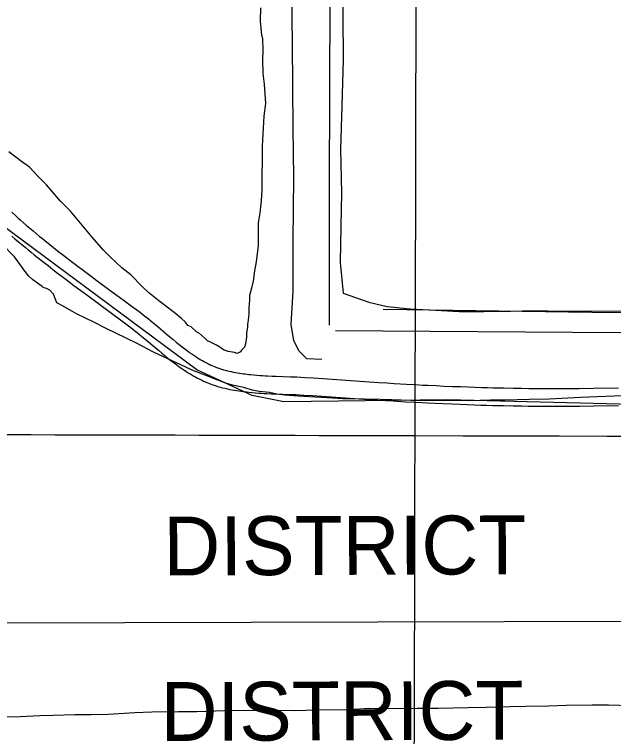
# Model space of a CAD drawing. Extents: x 3180038 to 3217926, y 922069 to 947485.
# Drawn here: x 3186224 to 3187243, y 939132 to 940353 of the extents above; entities that cross this region are included whole.
import ezdxf

# ---------------------------------------------------------------- set-up
doc = ezdxf.new("R2010")
doc.units = 0
for name, color, linetype in [('V-GRID-MAJR', 7, 'Continuous'), ('V-ROAD-CNTR', 7, 'Continuous'), ('V-SITE-VEGE', 7, 'Continuous'), ('V-TOPO-BNDY', 7, 'Continuous'), ('V-TOPO-GNAM-IDEN', 7, 'Continuous'), ('V-TOPO-SHOR', 7, 'Continuous')]:
    doc.layers.add(name, color=color, linetype=linetype)

msp = doc.modelspace()

# ---------------------------------------------------------------- linework, layer by layer
at = {"layer": 'V-GRID-MAJR'}
for points in [[(3186873.701, 927512.849), (3186889.572, 933574.8250000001), (3186905.4450000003, 939637.892), (3186921.319, 945701.009), (3186921.322, 945702.052)], [(3184296.343, 939644.818), (3186905.4450000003, 939637.892), (3192123.65, 939624.61), (3197341.857, 939612.087), (3202560.066, 939600.323), (3207778.276, 939589.318), (3212996.488, 939579.072), (3215605.594, 939574.233)]]:
    msp.add_spline(points, degree=3, dxfattribs=at)
at = {"layer": 'V-ROAD-CNTR'}
for points in [[(3186746.885000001, 939767.4489999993), (3186721.199000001, 939768.0739999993), (3186708.247000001, 939781.1749999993), (3186699.546000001, 939798.6749999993), (3186694.671000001, 939826.5769999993), (3186698.024000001, 939883.5709999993), (3186698.067000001, 939968.6919999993), (3186699.183000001, 940076.4899999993), (3186698.128000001, 940160.1839999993), (3186697.422000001, 940230.9029999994), (3186696.983000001, 940304.3829999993), (3186696.046000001, 940387.7139999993), (3186696.594000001, 940475.4709999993), (3186697.387000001, 940574.9899999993), (3186699.457000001, 940693.8269999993), (3186700.256000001, 940805.5919999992), (3186701.929000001, 940943.8819999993), (3186703.848000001, 941059.5979999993), (3186705.089000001, 941213.9799999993), (3186705.210000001, 941341.5989999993)], [(3186219.9015233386, 940017.2039377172), (3186226.0895109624, 940011.5429490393), (3186230.746501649, 940007.3529574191), (3186234.2434946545, 940004.2479636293), (3186239.549484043, 939999.6089729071), (3186244.9024733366, 939995.0179820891), (3186250.612461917, 939990.1959917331), (3186256.177450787, 939985.5450010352), (3186261.5914399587, 939981.0650099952), (3186266.8574294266, 939976.7480186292), (3186271.975419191, 939972.5860269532), (3186276.9494092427, 939968.5740349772), (3186281.774399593, 939964.7110427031), (3186291.1893807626, 939957.2480576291), (3186300.050363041, 939950.307071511), (3186308.3943463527, 939943.8400844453), (3186316.2473306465, 939937.8050965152), (3186323.6343158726, 939932.1711077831), (3186330.5733019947, 939926.9131182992), (3186343.655275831, 939917.0771379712), (3186355.139252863, 939908.5111551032), (3186365.216232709, 939901.0331700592), (3186382.9261972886, 939887.9531962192)], [(3186219.911523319, 939976.9290182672), (3186225.4585122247, 939972.1720277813), (3186231.3145005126, 939967.2260376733), (3186236.997489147, 939962.4770471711), (3186242.5194781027, 939957.909056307), (3186247.883467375, 939953.5100651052), (3186253.095456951, 939949.2720735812), (3186258.157446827, 939945.1900817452), (3186263.080436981, 939941.2470896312), (3186272.6214178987, 939933.684104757), (3186281.6103999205, 939926.643118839), (3186290.0643830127, 939920.0901319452), (3186298.011367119, 939913.9831441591), (3186305.478352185, 939908.2891555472), (3186312.499338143, 939902.9691661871), (3186325.6713117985, 939893.0651859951), (3186337.231288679, 939884.441203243), (3186347.366268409, 939876.9212182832), (3186365.104232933, 939863.8212444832)], [(3186382.913197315, 939887.9631961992), (3186409.5611440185, 939868.3282354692), (3186422.908117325, 939858.4692551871), (3186436.270090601, 939848.5532750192), (3186438.6850857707, 939846.7422786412), (3186443.3670764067, 939843.1562858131), (3186447.875067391, 939839.6192928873), (3186452.2000587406, 939836.1562998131), (3186456.357050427, 939832.772306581), (3186460.364042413, 939829.4653131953), (3186468.0190271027, 939823.0583260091), (3186482.216998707, 939811.0353500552), (3186488.3859863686, 939805.8353604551), (3186494.154974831, 939801.0273700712), (3186499.560964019, 939796.5933789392), (3186504.6339538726, 939792.5163870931), (3186509.3979443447, 939788.7733945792), (3186513.8759353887, 939785.3454014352), (3186518.086926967, 939782.2094077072), (3186522.0489190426, 939779.3444134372), (3186525.776911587, 939776.7294186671), (3186529.2879045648, 939774.3444234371), (3186532.592897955, 939772.1684277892), (3186535.7078917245, 939770.1844317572), (3186538.639885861, 939768.3764353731), (3186541.397880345, 939766.7294386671), (3186543.9988751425, 939765.226441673), (3186546.445870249, 939763.8564444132), (3186548.7488656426, 939762.6094469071), (3186550.9208612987, 939761.4684491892), (3186552.964857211, 939760.4274512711), (3186554.886853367, 939759.477453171), (3186556.695849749, 939758.6094549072), (3186558.3958463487, 939757.8164564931), (3186559.9638432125, 939757.1064579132), (3186563.029837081, 939755.772460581), (3186565.6878317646, 939754.6744627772), (3186568.028827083, 939753.7554646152), (3186570.091822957, 939752.9804661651), (3186571.900819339, 939752.3284674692), (3186573.4578162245, 939751.7894685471), (3186576.3128105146, 939750.8504704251), (3186578.426806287, 939750.1964717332), (3186579.9898031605, 939749.7364726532), (3186582.420798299, 939749.0594740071), (3186584.8527934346, 939748.4274752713), (3186588.8147855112, 939747.4744771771), (3186592.662777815, 939746.6164788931), (3186596.404770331, 939745.8424804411), (3186600.039763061, 939745.144481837), (3186603.5707559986, 939744.516483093), (3186607.001749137, 939743.9504842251), (3186610.335742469, 939743.4394852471), (3186613.572735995, 939742.9784861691), (3186616.7167297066, 939742.563486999), (3186619.771723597, 939742.1874877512), (3186622.737717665, 939741.8474884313), (3186625.5937119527, 939741.5434890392), (3186631.223700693, 939741.0034901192), (3186636.495690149, 939740.5624910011), (3186641.4596802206, 939740.1994917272), (3186646.130670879, 939739.8964923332), (3186650.522662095, 939739.6434928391), (3186654.6416538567, 939739.4294932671), (3186662.445638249, 939739.0754939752), (3186669.284624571, 939738.8064945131), (3186693.4935761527, 939737.9454962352), (3186699.607563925, 939737.7014967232), (3186704.221554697, 939737.4974971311), (3186711.136540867, 939737.1514978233), (3186718.048527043, 939736.7444986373), (3186732.9034973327, 939735.7815005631), (3186843.800275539, 939728.3105155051), (3186857.629247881, 939727.4185172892), (3186869.7302236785, 939726.6595188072), (3186890.921181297, 939725.3875213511), (3186906.8061495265, 939724.4895231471), (3186918.718125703, 939723.8545244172), (3186927.643107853, 939723.4005253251), (3186941.047081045, 939722.759526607), (3186954.4530542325, 939722.1705277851), (3186968.835025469, 939721.5835289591), (3186982.323998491, 939721.0645299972), (3186994.9669732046, 939720.6055309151), (3187006.818949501, 939720.201531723), (3187017.927927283, 939719.8475324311), (3187028.3579064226, 939719.5365330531)], [(3186365.117232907, 939863.811244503), (3186391.751179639, 939844.1862837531), (3186405.058153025, 939834.3573034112), (3186418.332126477, 939824.5073231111), (3186420.5651220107, 939822.8323264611), (3186424.987113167, 939819.4463332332), (3186429.239104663, 939816.1093399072), (3186433.3540964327, 939812.8143464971), (3186437.3390884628, 939809.5703529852), (3186441.188080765, 939806.3933593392), (3186448.6990657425, 939800.1083719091), (3186462.8550374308, 939788.1193958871), (3186469.114024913, 939782.8434064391), (3186475.0390130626, 939777.9054163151), (3186480.651001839, 939773.3034255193), (3186485.969991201, 939769.0284340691), (3186491.0119811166, 939765.0674419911), (3186495.797971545, 939761.4034493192), (3186500.3369624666, 939758.0234560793), (3186504.6449538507, 939754.9084623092), (3186508.732945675, 939752.0414680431), (3186512.6099379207, 939749.4064733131), (3186516.2869305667, 939746.9864781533), (3186519.771923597, 939744.766482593), (3186523.0739169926, 939742.7284866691), (3186526.2059107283, 939740.8594904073), (3186529.1689048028, 939739.1484938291), (3186531.973899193, 939737.5784969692), (3186534.628893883, 939736.1394998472), (3186537.136888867, 939734.8225024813), (3186539.508884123, 939733.6135048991), (3186541.750879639, 939732.5055071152), (3186543.867875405, 939731.4895091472), (3186545.8698714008, 939730.5565110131), (3186547.7918675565, 939729.6865127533), (3186551.315860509, 939728.1525158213), (3186554.477854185, 939726.8465184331), (3186557.2708485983, 939725.7495206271), (3186559.733843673, 939724.8245224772), (3186561.9108393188, 939724.0405240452), (3186563.861835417, 939723.3655253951), (3186567.192828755, 939722.2685275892), (3186569.756823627, 939721.4765291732), (3186571.7238196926, 939720.8965303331), (3186574.6268138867, 939720.0875319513), (3186577.5748079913, 939719.3235334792), (3186582.038799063, 939718.248535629), (3186586.3607904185, 939717.2845375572), (3186590.5407820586, 939716.4205392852), (3186594.5857739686, 939715.644540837), (3186598.500766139, 939714.9485422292), (3186602.285758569, 939714.3225434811), (3186605.9477512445, 939713.7615446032), (3186609.492744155, 939713.256545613), (3186612.920737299, 939712.803546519), (3186616.235730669, 939712.3955473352), (3186619.4437242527, 939712.0295480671), (3186622.5717179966, 939711.6955487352), (3186628.541706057, 939711.1235498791), (3186634.149694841, 939710.654550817), (3186639.3936843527, 939710.2695515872), (3186644.296674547, 939709.9525522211), (3186648.882665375, 939709.687552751), (3186653.1856567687, 939709.4655531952), (3186661.1756407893, 939709.1015539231), (3186668.162626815, 939708.8265544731), (3186692.361578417, 939707.9675561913), (3186698.347566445, 939707.7275566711), (3186702.809557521, 939707.5315570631), (3186709.504544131, 939707.1955577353), (3186716.1965307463, 939706.802558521), (3186730.925501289, 939705.8475604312), (3186841.8262794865, 939698.3745753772), (3186855.725251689, 939697.4785771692), (3186867.892227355, 939696.7155786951), (3186889.177184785, 939695.4375812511), (3186905.1601528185, 939694.535583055), (3186917.1561288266, 939693.8945843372), (3186926.165110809, 939693.4365852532), (3186939.671083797, 939692.7915865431), (3186953.1830567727, 939692.196587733), (3186967.647027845, 939691.6075889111), (3186981.202000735, 939691.0845899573), (3186993.9129753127, 939690.6235908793), (3187005.8309514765, 939690.2175916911), (3187017.0039291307, 939689.8615924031), (3187027.465908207, 939689.5505930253)], [(3187028.324906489, 939719.537533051), (3187038.0958869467, 939719.2685335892), (3187056.4058503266, 939718.8175344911), (3187072.413818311, 939718.4865351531), (3187086.4207902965, 939718.248535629), (3187098.674765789, 939718.0795359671), (3187109.3947443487, 939717.9635361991), (3187118.765725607, 939717.888536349), (3187135.1886927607, 939717.8145364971), (3187147.494668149, 939717.8105365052), (3187156.715649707, 939717.8375364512), (3187170.563622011, 939717.9245362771), (3187184.412594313, 939718.0745359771), (3187208.5075461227, 939718.4085353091), (3187250.717461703, 939719.0715339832)], [(3187027.4989081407, 939689.5495930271), (3187037.3138885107, 939689.2785935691), (3187055.7258516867, 939688.825594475), (3187071.849819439, 939688.4925951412), (3187085.9587912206, 939688.2525956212), (3187098.306766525, 939688.0815959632), (3187109.1127449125, 939687.9655961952), (3187118.5777259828, 939687.8885963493), (3187135.1166929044, 939687.8145964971), (3187147.5326680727, 939687.8105965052), (3187156.853649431, 939687.837596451), (3187170.8196214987, 939687.9265962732), (3187184.7825935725, 939688.076595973), (3187208.951545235, 939688.4125953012), (3187251.2034607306, 939689.0755939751)]]:
    msp.add_lwpolyline(points, dxfattribs=at)
at = {"layer": 'V-SITE-VEGE'}
for p, q in [((3186642.4820000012, 940364.6739999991), (3186642.304000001, 940342.0559999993)), ((3186642.304000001, 940342.0559999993), (3186644.5360000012, 940317.8019999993)), ((3186644.5360000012, 940317.8019999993), (3186646.1070000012, 940312.1349999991)), ((3186646.1070000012, 940312.1349999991), (3186646.756000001, 940291.9309999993)), ((3186646.756000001, 940291.9309999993), (3186645.827000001, 940276.589999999)), ((3186645.827000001, 940276.589999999), (3186646.449000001, 940253.1569999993)), ((3186646.449000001, 940253.1569999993), (3186648.726000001, 940234.5569999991)), ((3186648.726000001, 940234.5569999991), (3186650.895000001, 940202.224999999)), ((3186650.895000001, 940202.224999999), (3186648.300000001, 940180.4299999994)), ((3186648.300000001, 940180.4299999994), (3186646.4430000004, 940149.7449999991)), ((3186646.443000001, 940149.7449999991), (3186645.474000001, 940129.5579999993)), ((3186645.474000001, 940129.5579999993), (3186644.889000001, 940055.2359999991)), ((3186236.480000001, 940103.699999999), (3186214.796000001, 940120.0289999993)), ((3186250.137000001, 940093.8959999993), (3186236.480000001, 940103.699999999)), ((3186264.556000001, 940078.435999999), (3186250.137000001, 940093.8959999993)), ((3186278.983000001, 940063.7779999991), (3186264.556000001, 940078.435999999)), ((3186303.002000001, 940036.1199999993), (3186278.983000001, 940063.7779999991)), ((3186644.889000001, 940055.2359999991), (3186643.934000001, 940036.662999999)), ((3186319.832000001, 940019.0209999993), (3186303.002000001, 940036.1199999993)), ((3186643.934000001, 940036.662999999), (3186641.352000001, 940016.4859999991)), ((3186356.649000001, 939975.1079999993), (3186319.832000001, 940019.0209999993)), ((3186641.352000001, 940016.4859999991), (3186638.794000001, 939999.5409999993)), ((3186638.794000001, 939999.5409999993), (3186638.4890000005, 939960.7639999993)), ((3186375.865000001, 939953.1409999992), (3186356.649000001, 939975.1079999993)), ((3186224.4590000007, 939941.4469999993), (3186202.8260000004, 939964.2389999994)), ((3186387.887000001, 939940.9289999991), (3186375.865000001, 939953.1409999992)), ((3186638.489000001, 939960.7639999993), (3186635.040000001, 939933.3229999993)), ((3186232.454000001, 939930.8829999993), (3186224.459000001, 939941.4469999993)), ((3186407.134000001, 939923.0029999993), (3186387.887000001, 939940.9289999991)), ((3186236.4480000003, 939925.1939999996), (3186232.454000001, 939930.8829999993)), ((3186635.040000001, 939933.3229999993), (3186632.494000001, 939917.9929999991)), ((3186238.0450000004, 939922.7589999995), (3186236.4480000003, 939925.1939999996)), ((3186240.443000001, 939919.5089999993), (3186238.0450000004, 939922.7589999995)), ((3186249.246000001, 939908.9369999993), (3186240.443000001, 939919.5089999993)), ((3186422.388000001, 939910.763999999), (3186407.134000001, 939923.0029999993)), ((3186632.494000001, 939917.9929999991), (3186629.932000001, 939900.238999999)), ((3186255.658000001, 939902.4219999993), (3186249.246000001, 939908.9369999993)), ((3186267.710000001, 939894.2489999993), (3186255.658000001, 939902.4219999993)), ((3186441.622000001, 939891.2239999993), (3186422.388000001, 939910.763999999)), ((3186271.724000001, 939890.9859999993), (3186267.710000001, 939894.2489999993)), ((3186273.328000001, 939889.3559999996), (3186271.724000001, 939890.9859999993)), ((3186278.9700000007, 939887.6969999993), (3186273.328000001, 939889.3559999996)), ((3186452.850000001, 939880.6319999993), (3186441.622000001, 939891.2239999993)), ((3186629.932000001, 939900.238999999), (3186627.413000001, 939888.1419999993)), ((3186284.6060000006, 939885.2289999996), (3186278.9700000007, 939887.6969999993)), ((3186291.0130000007, 939877.9079999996), (3186284.6060000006, 939885.2289999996)), ((3186296.552000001, 939863.3219999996), (3186291.0130000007, 939877.9079999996)), ((3186469.707000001, 939866.7649999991), (3186452.8500000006, 939880.631999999)), ((3186627.413000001, 939888.1419999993), (3186624.085000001, 939876.047999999)), ((3186476.938000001, 939861.8599999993), (3186469.707000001, 939866.7649999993)), ((3186624.028000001, 939868.7799999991), (3186623.112000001, 939855.0519999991)), ((3186624.085000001, 939876.047999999), (3186624.028000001, 939868.7799999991)), ((3186298.969000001, 939862.4949999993), (3186296.552000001, 939863.3219999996)), ((3186306.2070000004, 939858.3989999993), (3186298.969000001, 939862.4949999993)), ((3186323.097000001, 939848.5699999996), (3186306.207000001, 939858.3989999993)), ((3186491.391000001, 939850.4359999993), (3186476.938000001, 939861.8599999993)), ((3186623.112000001, 939855.0519999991), (3186623.022000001, 939843.7409999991)), ((3186331.139000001, 939844.4659999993), (3186323.097000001, 939848.5699999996)), ((3186359.307000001, 939830.5109999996), (3186331.139000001, 939844.4659999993)), ((3186496.212000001, 939847.1649999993), (3186491.391000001, 939850.4359999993)), ((3186508.246000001, 939836.5689999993), (3186496.212000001, 939847.1649999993)), ((3186623.022000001, 939843.7409999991), (3186621.300000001, 939830.020999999)), ((3186381.837000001, 939819.0239999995), (3186359.307000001, 939830.5109999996)), ((3186515.471000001, 939830.856999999), (3186508.246000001, 939836.5689999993)), ((3186519.467000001, 939825.1699999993), (3186515.471000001, 939830.856999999)), ((3186621.300000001, 939830.020999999), (3186620.472000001, 939827.6049999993)), ((3186413.2290000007, 939804.2329999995), (3186381.837000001, 939819.0239999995)), ((3186525.101000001, 939822.7019999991), (3186519.4670000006, 939825.1699999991)), ((3186534.727000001, 939813.7399999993), (3186525.101000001, 939822.7019999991)), ((3186620.427000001, 939821.9499999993), (3186618.736000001, 939812.2669999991)), ((3186620.472000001, 939827.6049999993), (3186620.427000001, 939821.9499999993)), ((3186433.349000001, 939794.3799999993), (3186413.2290000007, 939804.2329999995)), ((3186538.747000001, 939811.283999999), (3186534.727000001, 939813.7399999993)), ((3186548.377000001, 939803.1289999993), (3186538.747000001, 939811.283999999)), ((3186618.676000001, 939804.998999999), (3186616.972000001, 939793.6999999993)), ((3186618.736000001, 939812.2669999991), (3186618.676000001, 939804.998999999)), ((3186460.700000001, 939779.6219999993), (3186433.349000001, 939794.3799999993)), ((3186552.384000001, 939799.0579999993), (3186548.377000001, 939803.1289999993)), ((3186556.4110000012, 939797.408999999), (3186552.384000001, 939799.0579999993)), ((3186562.043000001, 939794.133999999), (3186556.4110000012, 939797.408999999)), ((3186567.675000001, 939791.6669999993), (3186562.043000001, 939794.133999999)), ((3186573.305000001, 939788.3899999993), (3186567.675000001, 939791.6669999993)), ((3186616.972000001, 939793.6999999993), (3186615.311000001, 939788.059999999)), ((3186508.191000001, 939757.4339999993), (3186460.700000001, 939779.6219999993)), ((3186579.729000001, 939783.4929999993), (3186573.305000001, 939788.3899999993)), ((3186582.955000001, 939782.658999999), (3186579.729000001, 939783.4929999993)), ((3186587.788000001, 939781.0029999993), (3186582.955000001, 939782.658999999)), ((3186598.278000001, 939779.3069999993), (3186587.788000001, 939781.0029999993)), ((3186603.111000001, 939777.6519999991), (3186598.278000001, 939779.3069999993)), ((3186608.7860000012, 939780.0319999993), (3186603.111000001, 939777.6519999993)), ((3186610.427000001, 939783.2489999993), (3186608.7860000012, 939780.0319999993)), ((3186615.311000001, 939788.059999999), (3186610.427000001, 939783.2489999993)), ((3186526.707000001, 939749.2089999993), (3186508.191000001, 939757.4339999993)), ((3186551.674000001, 939739.3179999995), (3186526.707000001, 939749.2089999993)), ((3186565.363000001, 939733.5549999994), (3186551.674000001, 939739.3179999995)), ((3186583.891000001, 939726.9459999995), (3186565.363000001, 939733.5549999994)), ((3186595.175000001, 939723.6259999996), (3186583.891000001, 939726.9459999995)), ((3186614.5310000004, 939719.4339999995), (3186595.175000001, 939723.6259999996)), ((3186628.2320000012, 939715.2839999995), (3186614.5310000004, 939719.4339999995)), ((3186640.332000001, 939712.7649999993), (3186628.2320000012, 939715.2839999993)), ((3186658.092000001, 939711.0099999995), (3186640.332000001, 939712.7649999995)), ((3186670.190000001, 939708.4909999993), (3186658.092000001, 939711.0099999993)), ((3186683.909000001, 939706.7669999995), (3186670.190000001, 939708.4909999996)), ((3186706.517000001, 939704.9729999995), (3186683.909000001, 939706.7669999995)), ((3187280.125000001, 939706.1009999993), (3187186.3840000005, 939702.8019999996)), ((3186735.5860000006, 939703.1269999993), (3186706.517000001, 939704.9729999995)), ((3186755.775000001, 939702.1609999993), (3186735.5860000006, 939703.1269999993)), ((3186782.422000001, 939700.3339999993), (3186755.775000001, 939702.1609999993)), ((3186818.774000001, 939700.0469999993), (3186782.422000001, 939700.3339999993)), ((3186846.2340000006, 939699.0229999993), (3186818.774000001, 939700.0469999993)), ((3186865.6220000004, 939698.8699999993), (3186846.2340000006, 939699.0229999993)), ((3186897.929000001, 939697.8069999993), (3186865.6220000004, 939698.8699999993)), ((3186998.101000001, 939697.0159999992), (3186897.929000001, 939697.8069999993)), ((3187033.658000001, 939698.3509999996), (3186998.101000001, 939697.0159999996)), ((3187057.8920000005, 939698.1609999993), (3187033.658000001, 939698.3509999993)), ((3187099.9130000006, 939699.4429999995), (3187057.8920000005, 939698.1609999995)), ((3187133.0420000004, 939699.9919999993), (3187099.9130000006, 939699.4429999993)), ((3187186.3840000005, 939702.8019999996), (3187133.0420000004, 939699.9919999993)), ((3187132.1610000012, 939178.9109999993), (3187162.064000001, 939180.2909999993)), ((3187162.064000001, 939180.2909999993), (3187206.501000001, 939180.7479999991)), ((3187206.501000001, 939180.7479999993), (3187233.967000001, 939180.5309999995)), ((3187233.967000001, 939180.5309999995), (3187278.392000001, 939179.3719999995)), ((3186429.210000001, 939167.4929999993), (3186458.3050000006, 939168.8799999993)), ((3186458.3050000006, 939168.8799999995), (3186503.550000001, 939169.3309999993)), ((3186503.550000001, 939169.3309999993), (3186534.249000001, 939169.0889999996)), ((3186534.249000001, 939169.0889999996), (3186581.122000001, 939171.1449999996)), ((3186581.122000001, 939171.1449999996), (3186614.248000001, 939171.6879999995)), ((3186614.248000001, 939171.6879999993), (3186701.4950000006, 939170.9999999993)), ((3186701.4950000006, 939170.9999999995), (3186737.862000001, 939172.3289999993)), ((3186737.862000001, 939172.3289999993), (3186792.7990000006, 939172.7039999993)), ((3186792.7990000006, 939172.7039999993), (3186828.3650000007, 939174.8459999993)), ((3186828.3650000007, 939174.8459999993), (3186877.6420000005, 939174.4569999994)), ((3186877.6420000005, 939174.4569999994), (3186909.1540000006, 939175.0159999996)), ((3186909.1540000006, 939175.0159999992), (3186944.6970000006, 939174.7349999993)), ((3186944.6970000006, 939174.7349999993), (3186994.795000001, 939175.9559999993)), ((3186994.795000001, 939175.9559999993), (3187026.308000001, 939176.5169999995)), ((3187026.308000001, 939176.5169999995), (3187066.713000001, 939177.8129999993)), ((3187066.713000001, 939177.8129999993), (3187093.378000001, 939178.4089999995)), ((3187093.378000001, 939178.4089999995), (3187132.1610000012, 939178.9109999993)), ((3186211.022000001, 939160.3279999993), (3186234.457000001, 939160.9499999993)), ((3186234.457000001, 939160.9499999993), (3186267.592000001, 939162.3059999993)), ((3186267.592000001, 939162.3059999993), (3186290.218000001, 939162.9349999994)), ((3186290.218000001, 939162.9349999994), (3186327.391000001, 939164.2579999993)), ((3186327.391000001, 939164.2579999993), (3186354.857000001, 939164.0409999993)), ((3186354.857000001, 939164.0409999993), (3186383.947000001, 939164.6179999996)), ((3186383.947000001, 939164.6179999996), (3186429.210000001, 939167.4929999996))]:
    msp.add_line(p, q, dxfattribs=at)
for points in [[(3186780.403000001, 940528.8239999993), (3186781.564000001, 940440.9829999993), (3186782.440000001, 940350.7619999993), (3186782.916000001, 940276.7869999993), (3186780.616000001, 940197.8869999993), (3186778.889000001, 940124.4579999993), (3186780.507000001, 940049.9459999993), (3186779.180000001, 939993.4599999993), (3186777.812000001, 939931.8559999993), (3186783.014000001, 939879.7469999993)], [(3186783.014000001, 939879.7469999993), (3186826.763000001, 939864.3949999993), (3186857.956000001, 939857.3519999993), (3186896.852000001, 939853.3379999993), (3186940.173000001, 939850.7879999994), (3186980.056000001, 939848.7979999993), (3187022.075000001, 939848.6419999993), (3187067.448000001, 939849.0779999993), (3187107.534000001, 939850.1759999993), (3187152.809000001, 939849.2009999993)], [(3187152.809000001, 939849.2009999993), (3187203.6610000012, 939849.9459999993), (3187257.236000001, 939849.2579999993), (3187303.845000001, 939849.2439999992), (3187354.686000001, 939848.8429999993), (3187403.679000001, 939848.9859999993), (3187447.016000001, 939848.4679999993), (3187497.426000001, 939849.3049999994), (3187545.703000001, 939848.3059999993), (3187598.828000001, 939846.5629999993)]]:
    msp.add_lwpolyline(points, dxfattribs=at)
at = {"layer": 'V-TOPO-BNDY'}
msp.add_line((3184295.4583686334, 939315.6127140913), (3190109.406000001, 939329.5209999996), dxfattribs=at)
at = {"layer": 'V-TOPO-SHOR'}
for points in [[(3186775.486995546, 943234.2880313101), (3186771.8780290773, 942923.9169149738), (3186770.0735458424, 942344.677796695), (3186770.0735458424, 941835.8135245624), (3186762.8556129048, 941142.8919625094), (3186761.05112967, 940543.803528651), (3186759.2466464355, 940060.2020218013), (3186759.2466464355, 939928.4747456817), (3186759.2466464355, 939825.6192013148)], [(3187714.7205191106, 939568.9314612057), (3187581.1887597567, 939655.5466564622), (3187523.445296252, 939684.4183882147), (3186960.446527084, 939698.8542540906), (3186682.556108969, 939695.2452876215), (3186628.421611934, 939706.0721870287), (3186534.588483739, 939749.379784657), (3186144.820105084, 940038.0971021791), (3185866.9296869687, 940272.6799226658), (3185744.2248270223, 940348.4682185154), (3185386.937146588, 940543.3524078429), (3185181.2260578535, 940666.0572677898), (3185076.5660302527, 940759.8903959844), (3184961.0791032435, 940842.8966247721), (3184802.284578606, 940990.8642500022), (3184647.0990204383, 941128.0049758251), (3184538.830026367, 941207.4022381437), (3184372.817568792, 941312.0622657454), (3184304.24720588, 941366.1967627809)], [(3186851.2752913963, 939852.6864498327), (3187244.65263652, 939847.273000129), (3187333.072315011, 939849.0774833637), (3187459.3861414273, 939849.0774833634), (3187715.622760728, 939843.66403366), (3187841.936587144, 939838.2505839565), (3188125.2404549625, 939829.2281677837), (3188323.733610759, 939818.4012683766), (3188605.2329953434, 939812.9878186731), (3188688.2392241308, 939820.2057516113), (3188922.822044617, 939822.0102348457)], [(3186770.240604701, 939816.3773248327), (3187253.28735979, 939812.9993754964), (3187370.603000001, 939819.7569999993)]]:
    msp.add_lwpolyline(points, dxfattribs=at)

# ---------------------------------------------------------------- texts
at = {"layer": 'V-TOPO-GNAM-IDEN'}
for p in [(3186477.885359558, 939400.2909177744), (3186473.044397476, 939119.2437635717)]:
    msp.add_text('DISTRICT', height=99.99980199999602, rotation=0.2034444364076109, dxfattribs=at).set_placement(p)

doc.saveas('drawing.dxf')
